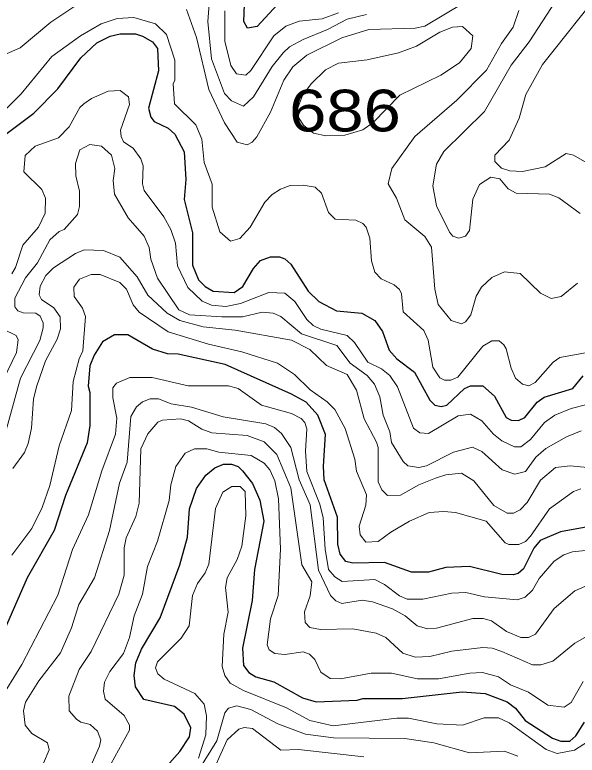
# Model space of a CAD drawing. Extents: x 577 to 602.9, y 7483.8 to 7511.6.
# Drawn here: x 580.554 to 581.632, y 7488.355 to 7489.775 of the extents above; entities that cross this region are included whole.
import ezdxf
from ezdxf.enums import TextEntityAlignment as Align

# ---------------------------------------------------------------- set-up
doc = ezdxf.new("R2010")
doc.units = 0
doc.header["$LTSCALE"] = 0.032
doc.layers.add('1', color=7, linetype='Continuous', lineweight=25)
doc.layers.add('2', color=7, linetype='Continuous', lineweight=13)
doc.layers.add('61', color=7, linetype='Continuous')

msp = doc.modelspace()

# ---------------------------------------------------------------- linework, layer by layer
at = {"layer": '1'}
for points in [[(581.0644, 7489.8024), (581.0183, 7489.7523), (581, 7489.7492), (580.9928, 7489.7619), (580.9944, 7489.7945)], [(580.5157, 7489.5305), (580.5905, 7489.5861), (580.6366, 7489.6331), (580.6803, 7489.6927), (580.7113, 7489.7213), (580.7368, 7489.7341), (580.7559, 7489.7388), (580.7853, 7489.7388), (580.7988, 7489.7341), (580.8179, 7489.7229), (580.8274, 7489.7102), (580.829, 7489.6673), (580.8099, 7489.5957), (580.8147, 7489.579), (580.8211, 7489.5702), (580.8481, 7489.5575), (580.8608, 7489.5464), (580.8783, 7489.5122), (580.8815, 7489.4589), (580.8783, 7489.4208), (580.8942, 7489.3571), (580.8942, 7489.2951), (580.9062, 7489.2665), (580.9189, 7489.2538), (580.934, 7489.245), (580.9745, 7489.2426), (580.9912, 7489.2538), (581.0111, 7489.2888), (581.0246, 7489.3039), (581.0437, 7489.311), (581.0612, 7489.311), (581.0716, 7489.307), (581.0827, 7489.2967), (581.1161, 7489.245), (581.1368, 7489.2251), (581.1702, 7489.2076), (581.2187, 7489.2029), (581.2441, 7489.1886), (581.2584, 7489.1679), (581.2711, 7489.1321), (581.2863, 7489.1154), (581.3197, 7489.09), (581.3491, 7489.0359), (581.3586, 7489.0263), (581.3713, 7489.024), (581.3817, 7489.0263), (581.4159, 7489.0582), (581.427, 7489.0637), (581.4509, 7489.0637), (581.4731, 7489.0438), (581.4954, 7489.0025), (581.5049, 7488.9977), (581.5192, 7488.9969), (581.5312, 7489.0025), (581.555, 7489.0319), (581.5685, 7489.0415), (581.6234, 7489.0582)], [(581.6592, 7488.7942), (581.5996, 7488.7838), (581.5606, 7488.7671), (581.5487, 7488.752), (581.5288, 7488.7123), (581.5184, 7488.7035), (581.5089, 7488.7011), (581.4874, 7488.7019), (581.4254, 7488.717), (581.3801, 7488.7154), (581.3467, 7488.7059), (581.3141, 7488.7059), (581.2624, 7488.725), (581.202, 7488.7234), (581.1884, 7488.7266), (581.1773, 7488.7409), (581.1733, 7488.76), (581.1725, 7488.8116), (581.1471, 7488.8832), (581.1455, 7488.9095), (581.1495, 7488.9699), (581.1344, 7489.0073), (581.1121, 7489.0319), (581.0843, 7489.0478), (580.9571, 7489.1043), (580.8672, 7489.1242), (580.8465, 7489.1249), (580.8179, 7489.1337), (580.7702, 7489.1615), (580.7447, 7489.1615), (580.7217, 7489.148), (580.7058, 7489.1226), (580.6978, 7489.1019), (580.6946, 7489.0629), (580.6978, 7489.051), (580.6978, 7488.9874), (580.6923, 7488.954), (580.6509, 7488.853), (580.6294, 7488.7862), (580.5778, 7488.6956), (580.5292, 7488.5842)], [(581.6234, 7489.0582), (581.6433, 7489.0828)], [(580.8887, 7488.8276), (580.9022, 7488.8665), (580.9197, 7488.892), (580.9372, 7488.9063), (580.9539, 7488.9134), (580.969, 7488.9134), (580.9817, 7488.9087), (580.9904, 7488.9007), (581.0095, 7488.8761), (581.0238, 7488.8442), (581.031, 7488.8037), (581.0135, 7488.7115), (581.0087, 7488.6518), (580.9904, 7488.5604), (580.992, 7488.527), (581.0024, 7488.5135), (581.0159, 7488.5055), (581.0501, 7488.496), (581.105, 7488.465), (581.1312, 7488.4578), (581.2099, 7488.461), (581.2211, 7488.4642), (581.2966, 7488.4642), (581.4111, 7488.4769), (581.4556, 7488.4737), (581.4978, 7488.4578), (581.5137, 7488.4451), (581.532, 7488.422), (581.5844, 7488.3878), (581.6003, 7488.3823), (581.6178, 7488.3823), (581.629, 7488.3926), (581.6457, 7488.4188)], [(580.8402, 7488.3282), (580.8704, 7488.3624), (580.8887, 7488.3902), (580.8911, 7488.4077), (580.8783, 7488.4339), (580.86, 7488.4483), (580.8012, 7488.4618), (580.7853, 7488.4864), (580.7829, 7488.5079), (580.7861, 7488.5325), (580.7964, 7488.5588), (580.8322, 7488.6184), (580.8704, 7488.7202), (580.8847, 7488.7735), (580.8887, 7488.8276)]]:
    msp.add_lwpolyline(points, dxfattribs=at)
at = {"layer": '2'}
for points in [[(581.6075, 7489.8279), (581.5399, 7489.7229), (581.5049, 7489.6784), (581.454, 7489.5893), (581.3761, 7489.513), (581.3618, 7489.4883), (581.3554, 7489.447), (581.3618, 7489.4088), (581.3872, 7489.3579), (581.3936, 7489.3508), (581.4047, 7489.3468), (581.4175, 7489.3508), (581.4254, 7489.3611), (581.4318, 7489.4215), (581.4445, 7489.4494), (581.466, 7489.4637), (581.4835, 7489.4605), (581.4994, 7489.4414), (581.5145, 7489.4327), (581.5789, 7489.4311), (581.5964, 7489.4239), (581.6377, 7489.3937)], [(581.6823, 7489.8271), (581.5654, 7489.68), (581.5336, 7489.6219), (581.5208, 7489.5766), (581.5017, 7489.5345), (581.4739, 7489.5058), (581.4739, 7489.4939), (581.4866, 7489.4812), (581.5025, 7489.4756), (581.5272, 7489.4748), (581.5701, 7489.4836), (581.6107, 7489.509), (581.625, 7489.5058), (581.6457, 7489.4939), (581.6616, 7489.4947), (581.6727, 7489.5027), (581.6878, 7489.5329), (581.7117, 7489.5631), (581.8453, 7489.6498), (581.9216, 7489.6776), (581.959, 7489.6975), (582.017, 7489.7436), (582.0862, 7489.7897)], [(580.9276, 7489.8136), (580.9237, 7489.7619), (580.9308, 7489.6903), (580.9555, 7489.6243), (580.969, 7489.61), (580.992, 7489.5997), (581.0111, 7489.618), (581.0469, 7489.676), (581.0684, 7489.7022), (581.0803, 7489.7134), (581.1065, 7489.7277), (581.1535, 7489.7468), (581.1908, 7489.7667), (581.2282, 7489.7754)], [(580.6764, 7489.7969), (580.6231, 7489.7611), (580.5642, 7489.7118), (580.5022, 7489.6848)], [(581.4159, 7489.7985), (581.3395, 7489.7531), (581.3212, 7489.7492), (581.2322, 7489.7468), (581.1805, 7489.7309), (581.1137, 7489.6975), (581.0867, 7489.6752), (581.0692, 7489.6498), (581.0437, 7489.5885), (581.0175, 7489.5408), (581.0087, 7489.5305), (580.9992, 7489.5257), (580.9801, 7489.5305), (580.9555, 7489.5679), (580.926, 7489.6315), (580.9022, 7489.7317), (580.8831, 7489.7849)], [(580.9563, 7489.7826), (580.9563, 7489.7245), (580.9682, 7489.6776), (580.9785, 7489.6617), (580.9968, 7489.6593), (581.0064, 7489.6681), (581.0501, 7489.7348), (581.0731, 7489.7531), (581.0986, 7489.7627), (581.1431, 7489.7674), (581.1741, 7489.7786)], [(581.6322, 7489.2601), (581.6011, 7489.2347), (581.5821, 7489.2307), (581.5614, 7489.241), (581.5224, 7489.2792), (581.4922, 7489.2824), (581.4684, 7489.2713), (581.4485, 7489.253), (581.4381, 7489.2355), (581.4278, 7489.1997), (581.4175, 7489.1862), (581.4103, 7489.1822), (581.3904, 7489.1886), (581.365, 7489.2196), (581.3586, 7489.249), (581.3523, 7489.3293), (581.3395, 7489.35), (581.3014, 7489.3818), (581.2855, 7489.4231), (581.2696, 7489.451), (581.2767, 7489.4804), (581.3204, 7489.5416), (581.4008, 7489.6116), (581.458, 7489.6688), (581.4866, 7489.7197), (581.5089, 7489.7515), (581.52, 7489.7834)], [(580.5364, 7489.5941), (580.5658, 7489.6235), (580.6247, 7489.6951), (580.6795, 7489.7348), (580.7193, 7489.7579), (580.7503, 7489.7682), (580.7821, 7489.7698), (580.8235, 7489.7579), (580.8449, 7489.7372), (580.8608, 7489.6879), (580.8608, 7489.6498), (580.8577, 7489.6426), (580.86, 7489.6044), (580.9006, 7489.5639), (580.9125, 7489.5368), (580.9165, 7489.4915), (580.9324, 7489.4502), (580.9324, 7489.4064), (580.9467, 7489.3587), (580.9674, 7489.3412), (580.9849, 7489.346), (581.0048, 7489.3675), (581.0334, 7489.416), (581.0469, 7489.4303), (581.0628, 7489.4406), (581.0819, 7489.4478), (581.1065, 7489.4486), (581.1296, 7489.4446), (581.1415, 7489.4327), (581.1551, 7489.3961), (581.1678, 7489.3834), (581.2075, 7489.381), (581.2211, 7489.3746), (581.2274, 7489.3675), (581.2346, 7489.3468), (581.2377, 7489.3031), (581.2441, 7489.2816), (581.256, 7489.2689), (581.2807, 7489.2569), (581.291, 7489.2482), (581.295, 7489.2402), (581.2982, 7489.2053), (581.3379, 7489.1695), (581.3459, 7489.1512), (581.3554, 7489.0995), (581.3682, 7489.0788), (581.3777, 7489.0741), (581.3896, 7489.0741), (581.4031, 7489.0804), (581.4509, 7489.1393), (581.4684, 7489.1496), (581.4819, 7489.1496), (581.4914, 7489.1424), (581.4954, 7489.1345), (581.5049, 7489.0971), (581.5137, 7489.078), (581.5272, 7489.0669), (581.5391, 7489.0637), (581.551, 7489.0701), (581.586, 7489.109), (581.5988, 7489.1178), (581.6576, 7489.1289)], [(581.5892, 7489.0073), (581.5693, 7488.9929), (581.5423, 7488.9603), (581.524, 7488.9468), (581.5113, 7488.9468), (581.4874, 7488.958), (581.4715, 7488.9707), (581.4493, 7488.9961), (581.427, 7489.0089), (581.4039, 7489.0057), (581.3467, 7488.9723), (581.33, 7488.9731), (581.3181, 7488.9826), (581.2871, 7489.0613), (581.2727, 7489.0836), (581.2568, 7489.0963), (581.2306, 7489.109), (581.2051, 7489.1464), (581.1908, 7489.1599), (581.1407, 7489.1719), (581.1256, 7489.179), (581.1137, 7489.1909), (581.0906, 7489.2251), (581.0716, 7489.241), (581.0405, 7489.2426), (580.9865, 7489.2212), (580.9586, 7489.2156), (580.9308, 7489.218), (580.9133, 7489.2259), (580.8855, 7489.2522), (580.8656, 7489.2935), (580.8616, 7489.3373), (580.8529, 7489.3635), (580.8394, 7489.3874), (580.802, 7489.4382), (580.7988, 7489.451), (580.7996, 7489.4852), (580.7956, 7489.4987), (580.7805, 7489.5194), (580.7622, 7489.5313), (580.7575, 7489.5416), (580.7567, 7489.5535), (580.7734, 7489.6028), (580.7718, 7489.618), (580.7559, 7489.6299), (580.7328, 7489.6283), (580.701, 7489.6148), (580.6859, 7489.6044), (580.6787, 7489.5973), (580.6581, 7489.5599), (580.6374, 7489.5392), (580.5929, 7489.5233), (580.5738, 7489.505), (580.5714, 7489.474), (580.6056, 7489.4398), (580.6127, 7489.4231), (580.6119, 7489.3945), (580.5992, 7489.3675), (580.569, 7489.3333), (580.5555, 7489.2903), (580.5483, 7489.2784)], [(580.5372, 7488.9786), (580.565, 7489.078), (580.6016, 7489.1504), (580.608, 7489.175), (580.608, 7489.1846), (580.6024, 7489.1973), (580.5945, 7489.2029), (580.5698, 7489.2037), (580.5595, 7489.2076), (580.5539, 7489.2148), (580.5539, 7489.2315), (580.5746, 7489.2705), (580.5976, 7489.2991), (580.6207, 7489.3436), (580.639, 7489.3595), (580.6485, 7489.3635), (580.674, 7489.3921), (580.6779, 7489.4072), (580.6779, 7489.4367), (580.6708, 7489.4661), (580.67, 7489.4899), (580.6787, 7489.5162), (580.6978, 7489.5265), (580.7201, 7489.5233), (580.7392, 7489.5058), (580.7455, 7489.4804)], [(580.7455, 7489.4804), (580.7424, 7489.4573), (580.7447, 7489.4311), (580.771, 7489.3858), (580.802, 7489.3508), (580.8115, 7489.3285), (580.8147, 7489.3062), (580.8274, 7489.2697), (580.868, 7489.2092), (580.8887, 7489.1997), (580.9507, 7489.1957), (580.9904, 7489.1957), (581.0278, 7489.2045), (581.0493, 7489.2029), (581.0636, 7489.1965), (581.1034, 7489.1631), (581.171, 7489.1409), (581.1964, 7489.1067), (581.229, 7489.0836), (581.2433, 7489.0669), (581.2537, 7489.0422), (581.26, 7489.0073), (581.2727, 7488.9755), (581.2759, 7488.9548), (581.2982, 7488.9182), (581.3069, 7488.9102), (581.3284, 7488.9071), (581.3427, 7488.9102), (581.3944, 7488.9365), (581.431, 7488.946), (581.4493, 7488.9373), (581.4882, 7488.9023), (581.5121, 7488.8943), (581.5328, 7488.8991), (581.5526, 7488.9269), (581.5717, 7488.9436), (581.6115, 7488.9659), (581.6393, 7488.977)], [(581.6846, 7488.9039), (581.6186, 7488.9102), (581.59, 7488.9071), (581.5614, 7488.8824), (581.5359, 7488.8395), (581.5224, 7488.826), (581.5097, 7488.8196), (581.4978, 7488.8196), (581.4723, 7488.8339), (581.4334, 7488.8816), (581.4103, 7488.8959), (581.3801, 7488.8928), (581.3602, 7488.8864), (581.3284, 7488.8737), (581.2934, 7488.8538), (581.268, 7488.853), (581.2576, 7488.8641), (581.2505, 7488.8792), (581.2505, 7488.9452), (581.2473, 7488.9556), (581.2234, 7489.0001), (581.2091, 7489.055), (581.1908, 7489.0852), (581.1511, 7489.1027), (581.1193, 7489.1329), (581.0843, 7489.1512), (580.9761, 7489.1703), (580.9149, 7489.1766), (580.8704, 7489.1886), (580.8457, 7489.2029), (580.8091, 7489.2371), (580.7885, 7489.2728), (580.7551, 7489.3102), (580.7241, 7489.3229), (580.6867, 7489.3245), (580.67, 7489.3174), (580.6278, 7489.2895), (580.6135, 7489.2752), (580.6024, 7489.2546), (580.6008, 7489.2379), (580.6048, 7489.2291), (580.6286, 7489.2132), (580.6406, 7489.1957), (580.6414, 7489.1727), (580.635, 7489.1528), (580.6127, 7489.1114), (580.596, 7489.0637), (580.5897, 7489.0383), (580.5857, 7488.9826), (580.5793, 7488.9532), (580.5722, 7488.9357), (580.5499, 7488.9047)], [(580.5483, 7488.7385), (580.5865, 7488.7902), (580.6064, 7488.8299), (580.6207, 7488.8721), (580.639, 7488.9484), (580.6628, 7489.016), (580.666, 7489.0717), (580.6772, 7489.1154), (580.6843, 7489.1305), (580.6891, 7489.1965), (580.6835, 7489.2124), (580.6676, 7489.2347), (580.6668, 7489.253), (580.6779, 7489.2681), (580.7002, 7489.2768), (580.7177, 7489.2768), (580.7551, 7489.2617), (580.7678, 7489.249), (580.7805, 7489.2188), (580.7925, 7489.2045), (580.8481, 7489.1671), (580.9252, 7489.1432), (580.9889, 7489.1289), (581.0572, 7489.1067), (581.0898, 7489.0852), (581.1201, 7489.0558), (581.1527, 7489.0327), (581.167, 7489.0184), (581.1869, 7488.9818), (581.2059, 7488.923), (581.2091, 7488.8999), (581.2282, 7488.8546), (581.2266, 7488.8347), (581.2139, 7488.7942), (581.2155, 7488.7775), (581.2266, 7488.7639), (581.2505, 7488.7647), (581.2743, 7488.783), (581.3101, 7488.8037), (581.3483, 7488.8204), (581.3761, 7488.8228), (581.3984, 7488.8204), (581.4572, 7488.8037), (581.4938, 7488.7623), (581.501, 7488.7592), (581.52, 7488.7592), (581.5328, 7488.7647), (581.5423, 7488.7751), (581.5789, 7488.8276), (581.625, 7488.8609), (581.6385, 7488.8657)], [(580.5316, 7489.1719), (580.5563, 7489.1599), (580.5603, 7489.152), (580.5571, 7489.1273), (580.5062, 7489.0224)], [(580.5229, 7488.4578), (580.5674, 7488.5294), (580.6366, 7488.6622), (580.6644, 7488.7496), (580.6954, 7488.8164), (580.7209, 7488.9007), (580.7471, 7488.9707), (580.7495, 7489.0017), (580.7416, 7489.0407), (580.7416, 7489.0597), (580.7487, 7489.0685), (580.7742, 7489.0796), (580.8171, 7489.0796), (580.8863, 7489.0637), (580.9634, 7489.0637), (580.9817, 7489.0582), (581.027, 7489.0263), (581.0843, 7489.0104), (581.1026, 7489.0009), (581.1097, 7488.9929), (581.1137, 7488.981), (581.1113, 7488.9381), (581.1137, 7488.8991), (581.1384, 7488.8363), (581.1447, 7488.8101), (581.1487, 7488.7504), (581.1551, 7488.7115), (581.167, 7488.6971), (581.1813, 7488.6884), (581.2441, 7488.6924), (581.2624, 7488.6828), (581.291, 7488.6606), (581.3061, 7488.6542), (581.3356, 7488.6542), (581.3912, 7488.6661), (581.4183, 7488.6669), (581.454, 7488.659), (581.5169, 7488.6534), (581.532, 7488.6582), (581.5463, 7488.6717), (581.559, 7488.694), (581.5876, 7488.7274), (581.6059, 7488.7393), (581.6226, 7488.7449), (581.66, 7488.7488)], [(581.1694, 7488.651), (581.159, 7488.6614), (581.136, 7488.7099), (581.1201, 7488.8355), (581.0986, 7488.8832), (581.0827, 7488.9452), (581.0652, 7488.9723), (581.0517, 7488.9834), (581.035, 7488.9906), (580.9531, 7489.0041), (580.8926, 7489.0224), (580.8537, 7489.0287), (580.829, 7489.0383), (580.8131, 7489.0383), (580.7988, 7489.0327), (580.7869, 7489.0232), (580.7765, 7489.0049), (580.7694, 7488.9174), (580.7543, 7488.8769), (580.7352, 7488.7862), (580.7066, 7488.6956), (580.6764, 7488.6439), (580.6628, 7488.5993), (580.6414, 7488.5516), (580.6, 7488.4976), (580.5746, 7488.457), (580.5706, 7488.4403), (580.5738, 7488.4125), (580.5865, 7488.3966), (580.6167, 7488.3791), (580.6199, 7488.3656), (580.6088, 7488.3401)], [(581.6727, 7489.0335), (581.6202, 7489.02), (581.5892, 7489.0073)], [(580.767, 7488.7719), (580.7861, 7488.8132), (580.7925, 7488.8387), (580.7956, 7488.9429), (580.8091, 7488.9715), (580.8282, 7488.9937), (580.837, 7488.9977), (580.8712, 7489.0001), (580.8871, 7488.9961), (580.9125, 7488.9802), (580.9316, 7488.9731), (580.9992, 7488.9683), (581.0318, 7488.9564), (581.0564, 7488.9317), (581.0827, 7488.8681), (581.1042, 7488.7202), (581.1232, 7488.6876), (581.1201, 7488.6606), (581.1089, 7488.6303), (581.1105, 7488.6097), (581.1193, 7488.6001), (581.1399, 7488.5962), (581.202, 7488.5977), (581.2465, 7488.589), (581.2648, 7488.581), (581.2974, 7488.5508), (581.3212, 7488.5429), (581.3491, 7488.5445), (581.3912, 7488.5548), (581.4509, 7488.562), (581.4691, 7488.5604), (581.4874, 7488.554), (581.5463, 7488.5286), (581.5622, 7488.5286), (581.5852, 7488.5357), (581.6274, 7488.5699), (581.6552, 7488.5858)], [(581.4501, 7488.5135), (581.4262, 7488.5127), (581.3658, 7488.5015), (581.326, 7488.5015), (581.2759, 7488.5127), (581.237, 7488.5127), (581.1781, 7488.5015), (581.1582, 7488.5023), (581.1407, 7488.5143), (581.1288, 7488.5389), (581.1185, 7488.5492), (581.1065, 7488.5532), (581.0716, 7488.5484), (581.0525, 7488.55), (581.0413, 7488.5572), (581.0374, 7488.5667), (581.0437, 7488.6168), (581.0588, 7488.6614), (581.0628, 7488.7504), (581.0596, 7488.8466), (581.0525, 7488.8816), (581.0429, 7488.9023), (581.0318, 7488.915), (581.0071, 7488.9301), (580.9451, 7488.9365), (580.9221, 7488.9429), (580.8982, 7488.9429), (580.8807, 7488.9341), (580.8624, 7488.9087), (580.8529, 7488.8737), (580.8497, 7488.8435), (580.8274, 7488.7655), (580.8084, 7488.717), (580.7988, 7488.6637), (580.7829, 7488.6224), (580.7734, 7488.581), (580.7622, 7488.55), (580.736, 7488.5158), (580.7257, 7488.4952), (580.7241, 7488.4777), (580.7272, 7488.4626), (580.7638, 7488.4316), (580.7734, 7488.4125), (580.7734, 7488.4029), (580.7384, 7488.3393)], [(580.9062, 7488.3497), (580.9197, 7488.3942), (580.9213, 7488.4308), (580.9165, 7488.453), (580.899, 7488.4737), (580.8402, 7488.5007), (580.8282, 7488.5111), (580.8235, 7488.523), (580.8274, 7488.5341), (580.8728, 7488.5795), (580.8879, 7488.6033), (580.8942, 7488.6614), (580.9038, 7488.6844), (580.9189, 7488.7051), (580.926, 7488.7218), (580.9388, 7488.8283), (580.9523, 7488.8594), (580.9698, 7488.8705), (580.9857, 7488.8705), (580.9952, 7488.8609)], [(580.9952, 7488.8609), (580.9968, 7488.814), (580.9889, 7488.756), (580.9801, 7488.7305), (580.961, 7488.6956), (580.9578, 7488.6765), (580.9626, 7488.6296), (580.9547, 7488.5874), (580.9515, 7488.5254), (580.9563, 7488.5079), (580.9666, 7488.4936), (580.992, 7488.4793), (581.0747, 7488.4459), (581.1193, 7488.422), (581.1638, 7488.4117), (581.2863, 7488.426), (581.3085, 7488.426), (581.3626, 7488.4156), (581.4119, 7488.4125), (581.4532, 7488.4268), (581.4811, 7488.4268), (581.5017, 7488.4172), (581.5725, 7488.3663), (581.5932, 7488.3584), (581.6266, 7488.3648), (581.6894, 7488.4053)], [(580.7002, 7488.3361), (580.7161, 7488.3727), (580.7185, 7488.3846), (580.7121, 7488.4013), (580.6986, 7488.4141), (580.6803, 7488.4188), (580.6724, 7488.4244), (580.6581, 7488.4403), (580.6573, 7488.4681), (580.6772, 7488.5198), (580.7002, 7488.554), (580.7535, 7488.6637), (580.7638, 7488.7003), (580.7638, 7488.7528), (580.767, 7488.7719)], [(581.6552, 7488.6828), (581.6274, 7488.6701), (581.5876, 7488.6367), (581.5518, 7488.5874), (581.5383, 7488.581), (581.524, 7488.581), (581.4962, 7488.5922), (581.4676, 7488.6129), (581.4517, 7488.6176), (581.4318, 7488.6176), (581.3618, 7488.5985), (581.3451, 7488.5977), (581.3252, 7488.6033), (581.3022, 7488.6224), (581.2775, 7488.6359), (581.2393, 7488.6494), (581.2195, 7488.6526), (581.1805, 7488.6463), (581.1694, 7488.651)], [(581.6433, 7488.4968), (581.6202, 7488.4562), (581.6067, 7488.4475), (581.5757, 7488.4514), (581.5383, 7488.4761), (581.5041, 7488.4904), (581.4811, 7488.5055), (581.4501, 7488.5135)], [(580.872, 7488.2717), (580.9411, 7488.383), (580.9563, 7488.4363), (580.9634, 7488.4451), (580.9793, 7488.4498), (581.0064, 7488.4427), (581.058, 7488.4156), (581.1113, 7488.3958), (581.1646, 7488.3886), (581.3014, 7488.387), (581.357, 7488.3791), (581.4254, 7488.36), (581.4922, 7488.3632), (581.5177, 7488.3536)], [(581.2226, 7488.352), (581.0978, 7488.3663), (581.0636, 7488.3648), (581.0095, 7488.4061), (580.9936, 7488.4085), (580.9833, 7488.4053), (580.961, 7488.3846), (580.9245, 7488.3043)]]:
    msp.add_lwpolyline(points, dxfattribs=at)
msp.add_lwpolyline([(581.1073, 7489.5631), (581.0978, 7489.5782), (581.0954, 7489.5949), (581.105, 7489.6203), (581.1217, 7489.6426), (581.1495, 7489.6696), (581.1741, 7489.6824), (581.229, 7489.6887), (581.2894, 7489.7022), (581.3236, 7489.715), (581.3682, 7489.742), (581.3928, 7489.7515), (581.4119, 7489.7523), (581.4318, 7489.7348), (581.4286, 7489.7102), (581.4063, 7489.6832), (581.3705, 7489.6593), (581.2918, 7489.6211), (581.2409, 7489.5687), (581.2211, 7489.5543), (581.1864, 7489.544), (581.1501, 7489.5432), (581.1264, 7489.548)], close=True, dxfattribs=at)

# ---------------------------------------------------------------- texts
at = {"layer": '61', "width": 1.2}
msp.add_text('686', height=0.08, dxfattribs=at).set_placement((581.1867, 7489.5514), align=Align.CENTER)

doc.saveas('drawing.dxf')
